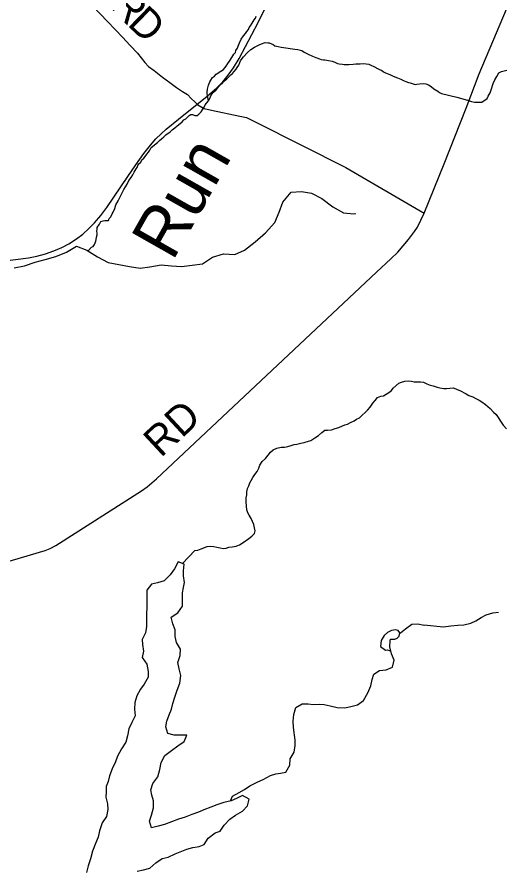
# Model space of a CAD drawing. Extents: x 1310247 to 1664935, y 235267 to 584339.
# Drawn here: x 1502798 to 1507738, y 382553 to 391172 of the extents above; entities that cross this region are included whole.
import ezdxf

# ---------------------------------------------------------------- set-up
doc = ezdxf.new("R2010")
doc.units = 0
for name, color, linetype in [('GM_X_Major_Lake', 7, 'Continuous'), ('GM_X_Minor_River', 7, 'Continuous'), ('GM_X_Minor_River_Text', 7, 'Continuous'), ('GM_X_Rail_Line', 7, 'Continuous'), ('GM_X_Township_Road', 7, 'Continuous'), ('GM_X_Township_Road_Text', 7, 'Continuous')]:
    doc.layers.add(name, color=color, linetype=linetype)

msp = doc.modelspace()

# ---------------------------------------------------------------- linework, layer by layer
at = {"layer": 'GM_X_Major_Lake'}
for points in [[(1504729.6, 382885), (1504798.7, 382936), (1504849.1, 382953.2), (1504890.2, 383014.8), (1504949.3, 383074), (1505006.1, 383115.2), (1505075, 383156.2), (1505128, 383209.6), (1505143.2, 383277.6), (1505075.5, 383312.8), (1505016.9, 383285.7), (1504962.4, 383260.5), (1504887.9, 383243.6), (1504817.3, 383220.7), (1504754.7, 383195.7), (1504686.1, 383168.7), (1504631.6, 383147.5), (1504565, 383122.5), (1504496.3, 383095.6), (1504429.8, 383074.6), (1504357.2, 383047.7), (1504288.5, 383020.8), (1504224.1, 383003.8), (1504155.6, 382988.8), (1504136.7, 383055.4), (1504155.7, 383115.3), (1504175, 383191.2), (1504176.1, 383261.5), (1504159, 383318), (1504149.8, 383370.3), (1504168.9, 383436.2), (1504220.1, 383503.6), (1504241.3, 383575.5), (1504254.5, 383647.5), (1504291.8, 383717.2), (1504356.8, 383768.3), (1504421.8, 383817.4), (1504486.6, 383860.5), (1504511.7, 383924.3), (1504449.5, 383923.3), (1504385.4, 383924.4), (1504321.5, 383941.5), (1504300.4, 384006.1), (1504311.4, 384066.1), (1504336.5, 384129.9), (1504357.5, 384185.7), (1504370.4, 384241.7), (1504391.6, 384307.6), (1504414.8, 384377.5), (1504442, 384447.3), (1504453.2, 384525.3), (1504434.3, 384593.9), (1504423.3, 384656.3), (1504444.4, 384726.2), (1504449.5, 384790.3), (1504408.5, 384857.2), (1504395.4, 384919.7), (1504394.5, 384985.9), (1504373.4, 385048.5), (1504356.5, 385115), (1504421.3, 385158.1), (1504470.6, 385225.5), (1504469.6, 385291.7), (1504470.7, 385359.9), (1504479.6, 385414), (1504490.5, 385466), (1504479.5, 385532.4), (1504478.3, 385582.6), (1504485.4, 385650.7), (1504425.6, 385671.7), (1504388.4, 385602.1), (1504345.3, 385540.6), (1504284.1, 385481.4), (1504217.6, 385462.5), (1504157.2, 385447.4), (1504110.1, 385388), (1504108.4, 385279.6), (1504109.3, 385213.4), (1504104.2, 385147.3), (1504105.2, 385083), (1504106.2, 385020.8), (1504095.1, 384954.8), (1504062, 384889.1), (1504065.2, 384838.8), (1504076.1, 384770.4), (1504061, 384706.5), (1504108.1, 384639.5), (1504123, 384567), (1504122, 384508.8), (1504082.8, 384439.2), (1504043.8, 384387.6), (1504008.7, 384322), (1503989.5, 384254.1), (1503984.4, 384185.9), (1503991.3, 384117.5), (1503956.2, 384051.9), (1503927, 383986.1), (1503913.9, 383916.1), (1503896.8, 383852.2), (1503851.6, 383784.7), (1503814.3, 383713)], [(1503814.3, 383713), (1503791.3, 383653.2), (1503760.1, 383583.5), (1503730.9, 383513.7), (1503719.9, 383455.7), (1503699, 383403.8), (1503698.2, 383353.7), (1503693.3, 383297.6), (1503710.2, 383229), (1503713.4, 383174.8), (1503700.1, 383100.8), (1503659, 383037.2), (1503629.6, 382959.4), (1503616.6, 382895.4), (1503591.4, 382829.6), (1503560.1, 382753.8), (1503538.8, 382673.9), (1503515.6, 382604), (1503498.4, 382536)], [(1504012.2, 382551.6), (1504074.5, 382562.6), (1504141, 382581.6), (1504200.1, 382634.8), (1504264.9, 382677.9), (1504325.3, 382691), (1504394.1, 382724), (1504446.6, 382745.2), (1504513.2, 382772.1), (1504573.6, 382789.2), (1504638, 382800.2), (1504688.5, 382819.4), (1504729.6, 382885)]]:
    msp.add_lwpolyline(points, dxfattribs=at)
at = {"layer": 'GM_X_Minor_River'}
for points in [[(1504732.4, 390327.3), (1504719.5, 390398.6), (1504719.8, 390414.7), (1504722.3, 390444.8), (1504731, 390484.7), (1504745.6, 390518.6), (1504755.9, 390534.5), (1504772.4, 390562.3), (1504792.7, 390576), (1504811.1, 390595.7), (1504857.8, 390625), (1504884.2, 390642.6), (1504896.5, 390660.4), (1504910.9, 390678.2), (1504929.3, 390702), (1504945.8, 390727.8), (1504968.5, 390763.5), (1504987.1, 390797.3), (1505003.5, 390815.1), (1505009.8, 390835), (1505024.2, 390856.8), (1505030.6, 390878.8), (1505045.3, 390912.6), (1505063.9, 390948.4), (1505086.6, 390982.1), (1505105.1, 391007.9), (1505119.4, 391027.7), (1505135.8, 391045.5), (1505144.2, 391065.4), (1505156.5, 391083.2), (1505175, 391109), (1505193.7, 391144.8), (1505206, 391162.6), (1505214.3, 391180.6)], [(1503515.1, 388812.8), (1503549.3, 388847.8), (1503565.5, 388855.6), (1503581.9, 388877.4), (1503588.2, 388893.3), (1503594.5, 388911.3), (1503598.8, 388927.2), (1503601.2, 388951.3), (1503605.6, 388973.3), (1503605.9, 388991.3), (1503604.2, 389011.5), (1503608.6, 389031.4), (1503608.9, 389047.5), (1503629.5, 389083.2), (1503644, 389107.1), (1503666.2, 389116.7), (1503686.3, 389118.4), (1503702.4, 389118.1), (1503722.5, 389119.8), (1503728.8, 389137.7), (1503745.2, 389155.5), (1503759.7, 389185.3), (1503770, 389201.2), (1503786.7, 389241), (1503797.4, 389277), (1503820.1, 389316.7), (1503838.9, 389356.5), (1503855.5, 389392.4), (1503878.2, 389430.1), (1503894.8, 389457.9), (1503911.3, 389485.7), (1503928, 389523.5), (1503950.6, 389553.2), (1503967.1, 389581.1), (1503981.5, 389604.9), (1503989.9, 389622.8), (1504000.2, 389638.7), (1504012.5, 389654.5), (1504018.8, 389672.5), (1504029.1, 389690.3), (1504047.5, 389708.1), (1504059.9, 389729.9), (1504078.3, 389747.7), (1504092.6, 389765.5), (1504109.1, 389789.3), (1504125.5, 389809.1), (1504137.8, 389828.9), (1504152.3, 389854.8), (1504217.4, 389905.8), (1504235.8, 389925.5), (1504258.2, 389943.2), (1504280.6, 389962.9), (1504301, 389982.6), (1504343.7, 390013.9), (1504364.1, 390033.6), (1504390.5, 390055.2), (1504415, 390074.9), (1504447.5, 390098.4), (1504465.8, 390114.1), (1504484.2, 390133.9), (1504504.5, 390145.6), (1504520.8, 390163.3), (1504537.2, 390179.1), (1504555.4, 390188.8), (1504571.4, 390188.5), (1504595.4, 390180.1), (1504617.5, 390179.7), (1504633.7, 390191.5), (1504658.2, 390215.1), (1504676.7, 390240.9), (1504687.1, 390262.8), (1504699.5, 390284.6), (1504730.3, 390324.2), (1504742.6, 390342.1), (1504748.9, 390360), (1504757.2, 390375.9), (1504767.6, 390393.8), (1504784, 390413.6), (1504808.5, 390439.2), (1504849.5, 390488.7), (1504875.9, 390512.3), (1504894.3, 390528), (1504916.7, 390547.7), (1504937.1, 390567.4), (1504957.5, 390589.1), (1504973.8, 390600.9), (1504992.2, 390622.6), (1505010.7, 390646.4), (1505023, 390662.2), (1505037.4, 390686), (1505047.9, 390711.9), (1505056.2, 390729.9), (1505072.7, 390755.6), (1505087, 390771.5), (1505127.9, 390812.9), (1505160.5, 390844.4), (1505197.1, 390867.8), (1505243.7, 390893.1), (1505267.9, 390902.7), (1505306.2, 390914.1), (1505330.3, 390913.7)], [(1505330.3, 390913.7), (1505346.3, 390911.4), (1505384.2, 390894.7), (1505402.1, 390882.3), (1505438, 390873.7), (1505468, 390867.1), (1505490.1, 390864.7), (1505536.2, 390859.9), (1505556.2, 390855.5), (1505606.2, 390848.6), (1505636.3, 390846.1), (1505674.2, 390833.4), (1505700.1, 390818.9), (1505737.9, 390798.2), (1505783.7, 390777.3), (1505799.7, 390771), (1505817.6, 390762.7), (1505853.5, 390750), (1505871.5, 390743.7), (1505893.5, 390739.3), (1505909.5, 390739), (1505929.6, 390736.6), (1505945.6, 390734.3), (1505983.6, 390725.6), (1506007.5, 390717.2), (1506035.4, 390704.7), (1506053.4, 390700.3), (1506087.5, 390697.7), (1506103.5, 390693.5), (1506151.6, 390692.6), (1506195.9, 390697.8), (1506220, 390699.4), (1506248.1, 390701), (1506264.2, 390700.7), (1506302.3, 390702), (1506324.4, 390699.6), (1506352.4, 390695.1), (1506374.4, 390686.7), (1506402.2, 390674.2), (1506448, 390651.3), (1506465.9, 390641), (1506481.9, 390634.6), (1506501.7, 390618.3), (1506527.6, 390605.8), (1506563.5, 390593.1), (1506593.4, 390578.5), (1506615.3, 390570.1), (1506643.2, 390557.6), (1506675.1, 390545), (1506710.9, 390528.3), (1506726.9, 390522), (1506752.8, 390511.5), (1506768.8, 390507.2), (1506800.7, 390496.6), (1506820.7, 390492.3), (1506836.8, 390494), (1506865, 390497.5), (1506909.2, 390500.8), (1506929.2, 390498.4), (1506955.2, 390487.9), (1506981, 390471.4), (1507010.7, 390448.8), (1507048.4, 390424.1), (1507068.3, 390411.7), (1507088.2, 390401.3)], [(1507088.2, 390401.3), (1507243.5, 390362), (1507277.5, 390353), (1507313.4, 390341.9), (1507349.3, 390332.8), (1507389.2, 390319.6), (1507419.2, 390314.8), (1507459.4, 390313.6), (1507493.7, 390314.6), (1507549, 390349.2), (1507559.7, 390375), (1507578.8, 390408.6), (1507593.9, 390446.3), (1507609.5, 390500.1), (1507626.7, 390539.8), (1507645.7, 390573.4), (1507666.8, 390609), (1507693.4, 390624.3), (1507746.1, 390636.8)], [(1503082.2, 388726.1), (1503190.5, 388754.2), (1503296.7, 388800.3), (1503399, 388860.5), (1503503.2, 388820.4), (1503609.5, 388752.2), (1503719.8, 388696), (1503826, 388676), (1503934.3, 388653.9), (1504040.6, 388635.9), (1504140.8, 388651.9), (1504253.1, 388670), (1504357.4, 388661.9), (1504459.6, 388655.9), (1504565.9, 388668), (1504670.2, 388682), (1504774.4, 388750.2), (1504884.7, 388782.3), (1504997, 388776.3), (1505097.2, 388820.4), (1505205.5, 388904.6), (1505307.7, 388994.9), (1505404, 389097.1), (1505446.1, 389203.4), (1505482.1, 389303.7), (1505568.3, 389404), (1505670.6, 389410), (1505772.8, 389396), (1505877.1, 389339.8), (1505989.4, 389255.6), (1506097.7, 389195.4), (1506199.9, 389185.4), (1506222, 389189.4)], [(1502769.4, 388641.8), (1502871.7, 388661.9), (1502979.9, 388698), (1503082.2, 388726.1)], [(1504912, 385811.2), (1504938.3, 385820.6), (1504972.6, 385825.8), (1505011, 385832.8), (1505045.5, 385844), (1505082.2, 385867.2), (1505139.6, 385909.9), (1505170.3, 385931.2), (1505197.1, 385958.6), (1505203.8, 385986.6), (1505198.5, 386014.8), (1505189.3, 386049.2), (1505176.1, 386081.6), (1505162.7, 386110.1), (1505143.5, 386142.7), (1505130.1, 386169.1), (1505120.7, 386197.5), (1505112.6, 386274), (1505113.7, 386318.1), (1505118.5, 386348.1), (1505121.3, 386378.1), (1505128.1, 386412.1), (1505138.9, 386439.9), (1505151.7, 386469.7), (1505162.4, 386495.5), (1505179.2, 386525.2), (1505200.1, 386554.8), (1505225, 386586.3), (1505239.9, 386620.1), (1505252.7, 386649.8), (1505275.8, 386687.4), (1505308.7, 386716.7), (1505335.7, 386750.1), (1505358.6, 386781.7), (1505387.3, 386805), (1505423.9, 386822.2), (1505466.4, 386831.1), (1505500.6, 386832.3), (1505532.8, 386837.5), (1505569.3, 386848.6), (1505597.6, 386855.9), (1505623.8, 386859.3), (1505664.3, 386870.3), (1505698.7, 386877.5), (1505741.3, 386892.4), (1505767.5, 386897.8), (1505806.4, 386924.9), (1505843.2, 386948.1), (1505878.1, 386979.3), (1505906.8, 387000.7), (1505935, 387002), (1505975.3, 387007), (1506011.8, 387020.1), (1506048.2, 387029.2), (1506084.8, 387044.3), (1506111.2, 387055.7), (1506137.5, 387063.1), (1506168, 387078.4), (1506202.7, 387097.5), (1506229.2, 387113), (1506257.7, 387126.3), (1506342.1, 387206.4), (1506367, 387235.9), (1506394.1, 387273.4), (1506416.9, 387300.9), (1506439.7, 387330.4), (1506474.3, 387345.6), (1506500.5, 387349), (1506529, 387364.3), (1506555.6, 387383.7), (1506582.2, 387401.1), (1506596.9, 387426.8), (1506654.4, 387475.5), (1506682.9, 387486.9), (1506717.3, 387498), (1506751.5, 387499.2), (1506783.6, 387498.4), (1506811.6, 387491.6), (1506873.9, 387490.1), (1506905.9, 387485.2), (1506939.7, 387470.3), (1506971.5, 387457.5), (1507001.5, 387448.7), (1507043.4, 387437.6), (1507069.3, 387428.9), (1507109.3, 387421.9), (1507137.5, 387423.2), (1507171.7, 387426.3), (1507208, 387429.4), (1507245.8, 387412.4), (1507271.6, 387401.7), (1507335.1, 387368), (1507362.8, 387351.2), (1507404.7, 387340.1), (1507434.5, 387323.3), (1507466.1, 387304.5), (1507493.9, 387289.7), (1507531.4, 387260.6), (1507578.6, 387221.3), (1507613.9, 387184.3), (1507639.4, 387159.5)], [(1507639.4, 387159.5), (1507658.7, 387129), (1507683.9, 387092.2), (1507709, 387053.4), (1507744.3, 387016.4)], [(1504470.8, 385655.8), (1504595.8, 385787.1), (1504626.1, 385792.4), (1504658.6, 385805.6), (1504719.4, 385828.2), (1504753.7, 385831.3), (1504785.8, 385828.5), (1504817.8, 385821.7), (1504849.7, 385812.8), (1504881.7, 385808), (1504912, 385811.2)], [(1506906.9, 385035.7), (1507108.4, 385017.8), (1507182.7, 385026.5), (1507253.1, 385035.3), (1507311.3, 385038.3), (1507381.8, 385055.1), (1507434.3, 385076.2), (1507489.1, 385111.3), (1507539.7, 385136.5), (1507604.2, 385157.4), (1507662.6, 385166.4)], [(1506663.4, 384949.1), (1506672.2, 384956.6), (1506723.1, 384997.9), (1506786.1, 385042.9), (1506848.4, 385045.9), (1506912.5, 385034.7)], [(1506580.3, 384745.5), (1506565.5, 384816), (1506566.5, 384876.2), (1506572.8, 384892.1), (1506615, 384893.4), (1506639.2, 384903), (1506659.6, 384922.7), (1506664.2, 384954.8), (1506650.6, 384981.1), (1506622.6, 384987.6), (1506580.3, 384980.3), (1506541.8, 384958.9), (1506507.2, 384929.4), (1506476.2, 384879.7), (1506469.2, 384819.7)], [(1506469.2, 384819.7), (1506520.7, 384782.6), (1506540.8, 384784.3), (1506574.5, 384773)], [(1504955.6, 383259), (1504973.8, 383306.2), (1505042.7, 383345.2), (1505097.4, 383374.3), (1505150.2, 383411.6), (1505231.2, 383452.3), (1505283.9, 383477.5), (1505358.8, 383516.3), (1505411.3, 383533.5), (1505461.6, 383538.6), (1505514, 383549.8), (1505553.3, 383619.3), (1505558.4, 383683.5), (1505599.7, 383753), (1505608.9, 383819.1), (1505607.8, 383873.3), (1505591.9, 384000), (1505589, 384064.2), (1505594.2, 384132.4), (1505615.4, 384202.3), (1505678.3, 384239.3), (1505738.5, 384238.3), (1505788.6, 384233.4), (1505850.9, 384236.3), (1505901, 384231.5), (1505961.1, 384220.4), (1506031, 384203.1), (1506107.2, 384197.8), (1506157.6, 384209), (1506238.3, 384229.6), (1506297.2, 384272.8), (1506342.7, 384350.2), (1506374, 384422), (1506387.1, 384483.9), (1506404.2, 384539.8), (1506461, 384575), (1506527.3, 384581.8), (1506592.1, 384610.8), (1506607.3, 384680.8), (1506580.3, 384745.5)]]:
    msp.add_lwpolyline(points, dxfattribs=at)
at = {"layer": 'GM_X_Rail_Line'}
msp.add_lwpolyline([(1502651, 388708.8), (1502914.7, 388742.4), (1502998.2, 388758.2), (1503083.6, 388782.6), (1503171, 388811.7), (1503248.5, 388847.4), (1503321.7, 388884.8), (1503398.6, 388934.9), (1503461.9, 388982.2), (1503519.6, 389033.3), (1503581.2, 389094.4), (1503644.4, 389168.6), (1503703.8, 389250), (1503917.7, 389562.3), (1503997.5, 389679.4), (1504079.4, 389796.6), (1504145.4, 389878.5), (1504201.5, 389941.7), (1504252.6, 389994.5), (1504304.9, 390040.7), (1504428.6, 390141.4), (1504720, 390374), (1504817.9, 390459.2), (1504875.7, 390518.6), (1504930.7, 390585.7), (1504985.6, 390661), (1505040.6, 390753.4), (1505233.1, 391118), (1505343.6, 391336.3)], dxfattribs=at)
at = {"layer": 'GM_X_Township_Road'}
for points in [[(1502448.4, 392943), (1502402.7, 392881.5), (1502358.8, 392784), (1502447.5, 392645.1), (1502745.8, 392219.8), (1502920, 391986.5), (1503106.1, 391762), (1503410.3, 391443), (1503862.3, 390970.4), (1503939.3, 390886.6), (1504014.1, 390807.7), (1504087.3, 390713.2), (1504125.4, 390673.8), (1504181.8, 390631.5), (1504267.8, 390566.6), (1504342.5, 390511.7), (1504410.1, 390462.3), (1504467.9, 390420.1), (1504518.7, 390391.9), (1504558.1, 390349.6), (1504592.6, 390317.6)], [(1506911.6, 389192.3), (1507112.6, 389690.7), (1507337.7, 390251.6), (1507469.2, 390600.2), (1507817.9, 391429.6), (1507869.8, 391555.8), (1508233.3, 392345.9), (1508348.4, 392649.4), (1508382.3, 392744.3), (1508409.4, 392777), (1508445.5, 392778.1), (1508483.9, 392762.3), (1508684.7, 392644.9), (1508808.9, 392563.7), (1508872.1, 392521.9), (1508919.5, 392508.4), (1508959, 392536.6)], [(1504592.6, 390317.6), (1504597.6, 390312.9), (1504623, 390284.8), (1504687.8, 390249.5), (1504764, 390232.6), (1505047.7, 390172.2), (1505117.5, 390159.3), (1505216.6, 390107.9), (1506119.8, 389654.5), (1506911.6, 389192.3)], [(1502383.6, 385583.9), (1503081.6, 385788.8), (1503132.1, 385807.5), (1503191, 385838), (1504053.9, 386388.5), (1504113.1, 386429), (1504205.3, 386510.7), (1506429.6, 388598), (1506575.2, 388730.4), (1506647.1, 388800.6), (1506752.5, 388928.1), (1506812.6, 389008.6), (1506843.8, 389051.8), (1506911.6, 389192.3)]]:
    msp.add_lwpolyline(points, dxfattribs=at)

# ---------------------------------------------------------------- texts
at = {"layer": 'GM_X_Minor_River_Text'}
msp.add_text('Run', height=499.76, rotation=60.45034, dxfattribs=at).set_placement((1504368.9, 388698.7))
at = {"layer": 'GM_X_Township_Road_Text'}
for s, rotation, p in [('R', 313.44051, (1503725.3, 391283.6)), ('D', 315.75091, (1503903.8, 391095.5)), ('RD', 42.90453, (1504249.9, 386717.5))]:
    msp.add_text(s, height=300, rotation=rotation, dxfattribs=at).set_placement(p)

doc.saveas('drawing.dxf')
